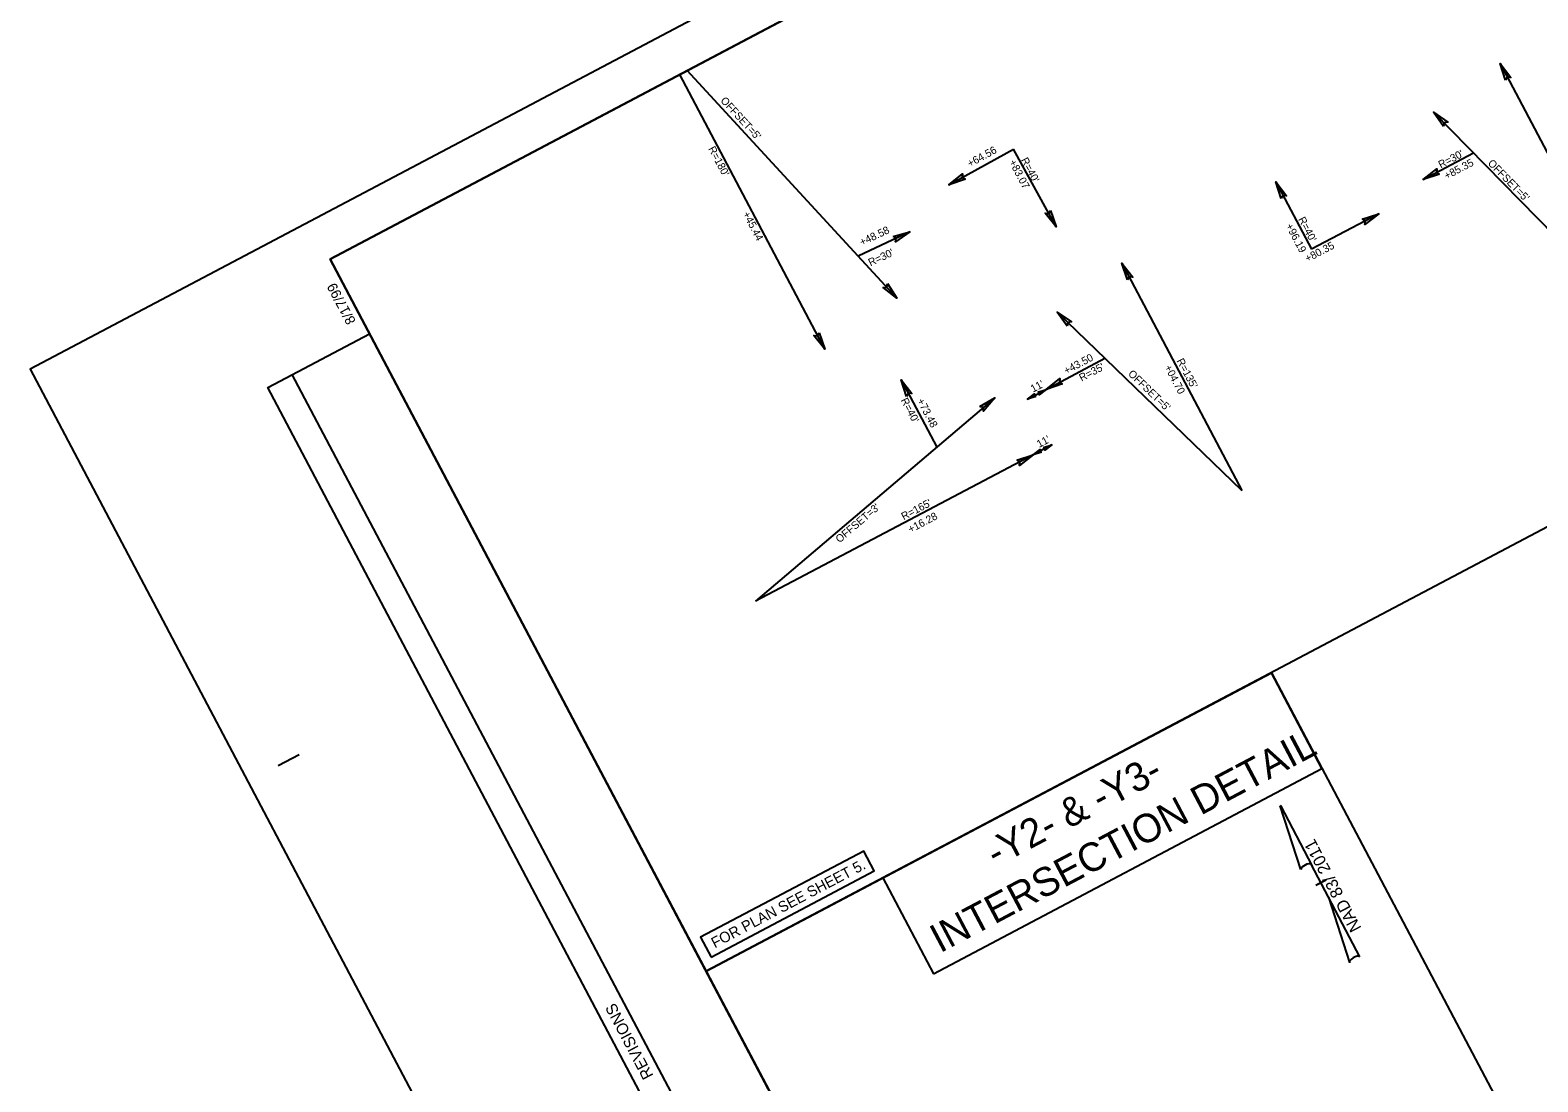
# Model space of a CAD drawing. Extents: x 1487555 to 1489555, y 497613 to 499367.
# Drawn here: x 1487555 to 1488347, y 498206 to 498759 of the extents above; entities that cross this region are included whole.
import ezdxf

# ---------------------------------------------------------------- set-up
doc = ezdxf.new("R2010")
doc.units = 0
for name, color, linetype in [('Prop Dimension', 7, 'Continuous'), ('Prop Dimension Text', 7, 'Continuous'), ('Prop Grid Mask', 7, 'Continuous'), ('Prop Horizontal Alignment Curve and Spiral Data', 7, 'Continuous'), ('Prop North Arrow NAD83 for Plan Sheets CELL', 7, 'Continuous'), ('Prop Terminator CELL', 7, 'Continuous'), ('Sheet Block Revision CELL', 7, 'Continuous'), ('Sheet Plan CELL', 7, 'Continuous'), ('Sheet Plot Border Outside CELL', 7, 'Continuous')]:
    doc.layers.add(name, color=color, linetype=linetype)

msp = doc.modelspace()

# ---------------------------------------------------------------- linework, layer by layer
at = {"layer": 'Prop Dimension'}
for p, q in [((1487972.5, 498591.48), (1487896.29, 498735.8)), ((1488010.45, 498618.3), (1487900.23, 498737.87)), ((1488327.5, 498741.61), (1488397.54, 498608.96)), ((1488292.53, 498716.07), (1488397.54, 498608.96)), ((1488037.79, 498677.85), (1488071.68, 498696.55)), ((1488094.2, 498655.74), (1488071.68, 498696.55)), ((1488287, 498680.64), (1488313.53, 498694.65)), ((1488209.64, 498679.37), (1488228.32, 498644)), ((1488263.69, 498662.68), (1488228.32, 498644)), ((1488017.25, 498653.17), (1487990.12, 498640.36)), ((1488128.74, 498636.66), (1488191.78, 498517.28)), ((1488094.62, 498611.01), (1488191.78, 498517.28)), ((1488088.86, 498570.36), (1488119.81, 498586.71)), ((1488012.7, 498575.39), (1488031.38, 498540.01)), ((1488079.13, 498565.23), (1488088.86, 498570.36)), ((1488061.83, 498565.95), (1487936.2, 498458.98)), ((1488091.84, 498541.16), (1488082.11, 498536.02)), ((1488082.11, 498536.02), (1487936.2, 498458.98))]:
    msp.add_line(p, q, dxfattribs=at)
at = {"layer": 'Prop Grid Mask'}
for points in [[(1488029.66, 498263.27), (1488233.85, 498371.08), (1488207.27, 498421.43), (1488003.08, 498313.61)], [(1487912.81, 498272.06), (1487998.51, 498317.31), (1487992.99, 498327.76), (1487907.29, 498282.51)]]:
    msp.add_lwpolyline(points, close=True, dxfattribs=at)
at = {"layer": 'Prop North Arrow NAD83 for Plan Sheets CELL'}
for p, q in [((1488211.99, 498351.6), (1488211.96, 498351.58)), ((1488211.99, 498351.6), (1488211.96, 498351.58)), ((1488222.71, 498317.96), (1488211.96, 498351.58)), ((1488211.99, 498351.6), (1488228.7, 498319.88)), ((1488237.36, 498303.42), (1488228.21, 498320.81)), ((1488228.7, 498319.88), (1488228.22, 498320.78)), ((1488230.65, 498309.72), (1488230.62, 498309.71)), ((1488233.01, 498310.96), (1488230.65, 498309.72)), ((1488230.69, 498309.74), (1488236, 498312.54)), ((1488237.36, 498303.42), (1488248.34, 498269.15)), ((1488253.84, 498272.22), (1488237.36, 498303.42))]:
    msp.add_line(p, q, dxfattribs=at)
for centre, start_param, end_param in [((1488225.63, 498319.08), 0.216388, 2.908219), ((1488251.21, 498270.52), 0.201328, 3.141593)]:
    msp.add_ellipse(centre, major_axis=(2.82, 1.46), ratio=0.461098, start_param=start_param, end_param=end_param, dxfattribs=at)
at = {"layer": 'Prop Terminator CELL'}
for points in [[(1488330.33, 498732.92), (1488327.5, 498741.61), (1488333.14, 498734.35), (1488331.19, 498734.62)], [(1488297.72, 498708.56), (1488292.53, 498716.07), (1488300, 498710.73), (1488298.06, 498710.43)], [(1488046.42, 498680.84), (1488037.79, 498677.85), (1488044.94, 498683.62), (1488044.71, 498681.66)], [(1488212.47, 498670.69), (1488209.64, 498679.37), (1488215.28, 498672.12), (1488213.33, 498672.39)], [(1488295.68, 498683.47), (1488287, 498680.64), (1488294.26, 498686.28), (1488293.99, 498684.33)], [(1488091.21, 498664.37), (1488094.2, 498655.74), (1488088.43, 498662.89), (1488090.39, 498662.66)], [(1488255.01, 498659.85), (1488263.69, 498662.68), (1488256.43, 498657.04), (1488256.7, 498658.99)], [(1488008.45, 498650.73), (1488017.25, 498653.17), (1488009.75, 498647.86), (1488010.1, 498649.79)], [(1488131.57, 498627.98), (1488128.74, 498636.66), (1488134.38, 498629.4), (1488132.43, 498629.67)], [(1488005.49, 498625.97), (1488010.45, 498618.3), (1488003.14, 498623.87), (1488005.1, 498624.11)], [(1488100.02, 498603.64), (1488094.62, 498611.01), (1488102.24, 498605.87), (1488100.3, 498605.52)], [(1487969.67, 498600.16), (1487972.5, 498591.48), (1487966.86, 498598.73), (1487968.81, 498598.46)], [(1488015.53, 498566.7), (1488012.7, 498575.39), (1488018.34, 498568.13), (1488016.39, 498568.4)], [(1488084.52, 498568.95), (1488088.86, 498570.36), (1488085.23, 498567.54), (1488085.36, 498568.52)], [(1488097.54, 498573.2), (1488088.86, 498570.36), (1488096.11, 498576), (1488095.84, 498574.05)], [(1488053.98, 498561.29), (1488061.83, 498565.95), (1488055.98, 498558.86), (1488055.82, 498560.82)], [(1488083.47, 498566.64), (1488079.13, 498565.23), (1488082.76, 498568.05), (1488082.62, 498567.07)], [(1488086.45, 498537.44), (1488082.11, 498536.02), (1488085.74, 498538.84), (1488085.61, 498537.86)], [(1488087.5, 498539.74), (1488091.84, 498541.16), (1488088.21, 498538.34), (1488088.35, 498539.31)], [(1488073.43, 498533.19), (1488082.11, 498536.02), (1488074.86, 498530.38), (1488075.13, 498532.33)]]:
    msp.add_lwpolyline(points, close=True, dxfattribs=at)
at = {"layer": 'Sheet Block Revision CELL'}
msp.add_line((1488061.82, 497878.97), (1487692.63, 498578.12), dxfattribs=at)
msp.add_lwpolyline([(1488048.96, 497872.15), (1487679.78, 498571.32), (1487733.31, 498599.61), (1488102.48, 497900.44)], close=True, dxfattribs=at)
at = {"layer": 'Sheet Plan CELL'}
for p, q in [((1487712.59, 498638.82), (1487712.59, 498638.82)), ((1487685.17, 498372.71), (1487696.23, 498378.57))]:
    msp.add_line(p, q, dxfattribs=at)
for points in [[(1489039.06, 499339.23), (1487712.59, 498638.82), (1488202.86, 497710.31), (1489529.32, 498410.71)], [(1488202.86, 497710.31), (1487712.58, 498638.79), (1488862.13, 499245.82), (1488932.21, 499113.13), (1489109.11, 499206.52), (1489529.32, 498410.71)], [(1487712.58, 498638.79), (1488388.76, 498995.83), (1488586.36, 498621.6), (1487910.18, 498264.56)], [(1487910.18, 498264.56), (1488207.27, 498421.43), (1488332.57, 498184.13), (1488035.48, 498027.26)]]:
    msp.add_lwpolyline(points, close=True, dxfattribs=at)
at = {"layer": 'Sheet Plot Border Outside CELL'}
msp.add_lwpolyline([(1488066.15, 497612.67), (1489554.86, 498398.74), (1489043.57, 499367.04), (1487554.86, 498580.97)], close=True, dxfattribs=at)

# ---------------------------------------------------------------- texts
at = {"layer": 'Prop Dimension Text'}
for s, rotation, p in [("OFFSET=5'", 312.6702, (1487917.44, 498721.89)), ("R=180'", 297.83509, (1487911.16, 498696.84)), ('+64.56', 28.89139, (1488048.86, 498686.98)), ("R=30'", 27.83509, (1488296.33, 498686.41)), ('+83.07', 297.83509, (1488069.22, 498689.84)), ("R=40'", 297.83509, (1488075.51, 498690.94)), ('+85.35', 27.83509, (1488299.41, 498680.57)), ("OFFSET=5'", 314.43293, (1488320.74, 498688.9)), ('+45.44', 297.83509, (1487929.24, 498662.59)), ('+48.58', 25.27223, (1487992.01, 498645.7)), ('+96.19', 297.83509, (1488214.66, 498656.32)), ("R=40'", 297.83509, (1488221.21, 498659.78)), ('+80.35', 27.83509, (1488226.24, 498637.04)), ("R=30'", 25.27223, (1487996.56, 498634.98)), ('+43.50', 27.83509, (1488099.47, 498578.13)), ("R=35'", 27.83509, (1488107.5, 498574.41)), ("R=135'", 297.83509, (1488157.36, 498585.4)), ("OFFSET=5'", 316.02996, (1488131.65, 498578.18)), ('+04.70', 297.83509, (1488150.93, 498582.01)), ("11'", 27.83509, (1488081.99, 498568.63)), ("R=40'", 297.83509, (1488012.35, 498564.67)), ('+73.48', 297.83509, (1488020.87, 498564.39)), ("11'", 27.83509, (1488085.21, 498539.59)), ("R=165'", 27.83509, (1488014.04, 498501.53)), ("OFFSET=3'", 40.41321, (1487980.28, 498489.45)), ('+16.28', 27.83509, (1488017.61, 498494.79))]:
    msp.add_text(s, height=4, rotation=rotation, dxfattribs=at).set_placement(p)
at = {"layer": 'Prop Horizontal Alignment Curve and Spiral Data'}
for s, height, p in [('INTERSECTION DETAIL', 15, (1488033.1, 498273.95)), ('-Y2- & -Y3-', 15, (1488062.41, 498319.11)), ('FOR PLAN SEE SHEET 5.', 5.625, (1487914.73, 498276.58))]:
    msp.add_text(s, height=height, rotation=27.83509, dxfattribs=at).set_placement(p)
at = {"layer": 'Prop North Arrow NAD83 for Plan Sheets CELL'}
msp.add_text('NAD 83/ 2011', height=6.375, rotation=117.7742, dxfattribs=at).set_placement((1488254.8, 498287.25))
at = {"layer": 'Sheet Block Revision CELL'}
msp.add_text('REVISIONS', height=6, rotation=117.83509, dxfattribs=at).set_placement((1487882.6, 498209.71))
at = {"layer": 'Sheet Plan CELL'}
msp.add_text('8/17/99', height=5.25, rotation=117.8351, dxfattribs=at).set_placement((1487726.18, 498606.17))

doc.saveas('drawing.dxf')
